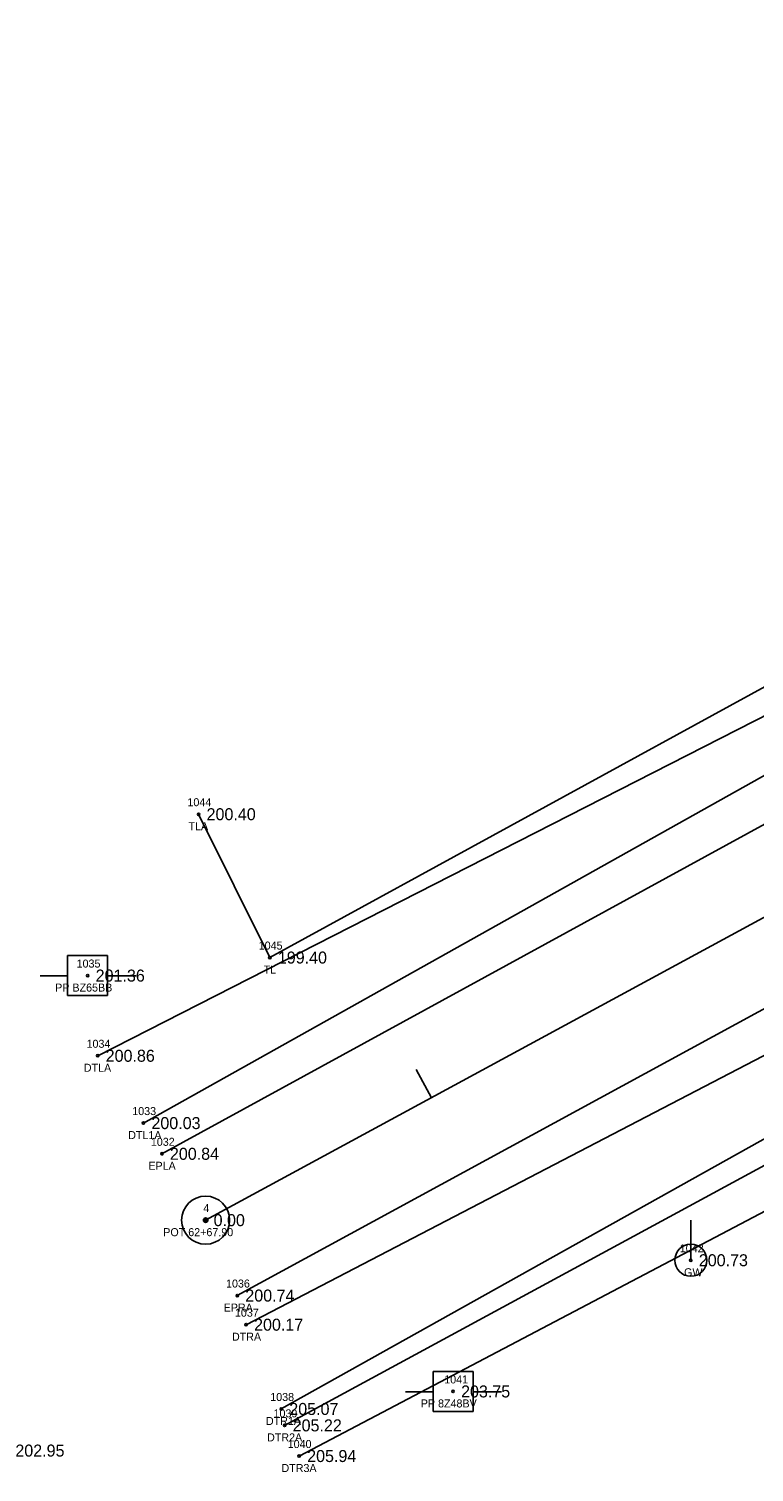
# Model space of a CAD drawing. Extents: x 2279339 to 2281902, y 1061267 to 1062892.
# Drawn here: x 2279537.7 to 2279628.3, y 1061401.7 to 1061582 of the extents above; entities that cross this region are included whole.
import ezdxf

# ---------------------------------------------------------------- set-up
doc = ezdxf.new("R2010")
doc.units = 0
for name, color, linetype in [('RD_EX_H2O', 7, 'Continuous'), ('RD_EX_H2O_txCode', 7, 'Continuous'), ('RD_EX_Road', 7, 'Continuous'), ('RD_EX_Road_txCode', 7, 'Continuous'), ('RD_EX_TX_H2O_ELEV', 7, 'Continuous'), ('RD_EX_TX_Road_ELEV', 7, 'Continuous'), ('RD_EX_TX_UT_ELEV', 7, 'Continuous'), ('RD_EX_TX_VEG_ELEV', 7, 'Continuous'), ('RD_EX_UT', 7, 'Continuous'), ('RD_EX_UT_txCode', 7, 'Continuous'), ('RD_EX_VEG', 7, 'Continuous'), ('RD_EX_VEG_txCode', 7, 'Continuous'), ('RD_HC_Cl', 7, 'Continuous'), ('RD_HC_Data', 7, 'Continuous'), ('RD_HC_Data_Tic', 7, 'Continuous'), ('RD_HC_Survey_ELEV', 7, 'Continuous'), ('RD_HC_txCode', 7, 'Continuous'), ('RD_SMD_Locator', 7, 'Continuous')]:
    doc.layers.add(name, color=color, linetype=linetype)

msp = doc.modelspace()

# ---------------------------------------------------------------- linework, layer by layer
at = {"layer": 'RD_EX_H2O'}
for points in [[(2279546.29, 1061453.71), (2279630.41, 1061496.6), (2279659.08, 1061511.93), (2279655.3, 1061525.45)], [(2279552, 1061445.3), (2279634.13, 1061491.29), (2279668.82, 1061510.33), (2279666.09, 1061516.71), (2279655.3, 1061525.45)], [(2279564.82, 1061420.11), (2279648.07, 1061463.42), (2279697.17, 1061487.92), (2279700.19, 1061484.6), (2279705.74, 1061483.55)], [(2279569.22, 1061409.58), (2279651.68, 1061455.72), (2279697.08, 1061482.41), (2279717.86, 1061447.1)], [(2279569.64, 1061407.53), (2279652.88, 1061452.64), (2279691.84, 1061472.85), (2279696.06, 1061472.47), (2279695.2, 1061463.42)], [(2279571.45, 1061403.7), (2279656.13, 1061448.23), (2279695.2, 1061463.42)]]:
    msp.add_lwpolyline(points, dxfattribs=at)
at = {"layer": 'RD_EX_Road'}
for points in [[(2279554.31, 1061441.46), (2279636.61, 1061486.51), (2279673.46, 1061506.76), (2279683.06, 1061512.21), (2279723.14, 1061533.54), (2279809.28, 1061580.29), (2279896.91, 1061627.91), (2279977.07, 1061671.02), (2280059.64, 1061715.57), (2280142.91, 1061760.72), (2280228.83, 1061807.06), (2280306.04, 1061849.18), (2280392.98, 1061896.71), (2280482.82, 1061945.75), (2280567.83, 1061991.78), (2280649.94, 1062036.55), (2280660.56, 1062042.19), (2280676.12, 1062050.66), (2280737.28, 1062083.64), (2280828.54, 1062132.77), (2280887.86, 1062164.61), (2280934.91, 1062190.9)], [(2279563.73, 1061423.75), (2279645.81, 1061468.43), (2279687.22, 1061491.24), (2279716.07, 1061507.1), (2279732.53, 1061515.67), (2279819.45, 1061563.03), (2279856.79, 1061583.22), (2279872.52, 1061591.57), (2279906, 1061609.76), (2279987.33, 1061653.65)]]:
    msp.add_lwpolyline(points, dxfattribs=at)
at = {"layer": 'RD_EX_UT'}
for p, q in [((2279547.53, 1061466.24), (2279542.53, 1061466.24)), ((2279542.53, 1061466.24), (2279542.53, 1061461.24)), ((2279547.53, 1061461.24), (2279547.53, 1061466.24)), ((2279539.1, 1061463.68), (2279542.57, 1061463.68)), ((2279547.46, 1061463.68), (2279551.1, 1061463.68)), ((2279542.53, 1061461.24), (2279547.53, 1061461.24)), ((2279620.36, 1061428.16), (2279620.36, 1061433.16)), ((2279593.17, 1061414.27), (2279588.17, 1061414.27)), ((2279588.17, 1061414.27), (2279588.17, 1061409.27)), ((2279593.17, 1061409.27), (2279593.17, 1061414.27)), ((2279584.73, 1061411.71), (2279588.2, 1061411.71)), ((2279593.09, 1061411.71), (2279596.73, 1061411.71)), ((2279588.17, 1061409.27), (2279593.17, 1061409.27))]:
    msp.add_line(p, q, dxfattribs=at)
msp.add_circle((2279620.36, 1061428.16), 2, dxfattribs=at)
at = {"layer": 'RD_EX_VEG'}
msp.add_lwpolyline([(2279558.89, 1061483.89), (2279567.79, 1061465.98), (2279895.37, 1061645.37), (2280383.77, 1061911.19), (2280927.05, 1062203.11)], dxfattribs=at)
at = {"layer": 'RD_HC_Cl'}
msp.add_line((2279559.77, 1061433.17), (2280939.55, 1062181.67), dxfattribs=at)
at = {"layer": 'RD_HC_Data'}
for radius in [3, 0.282]:
    msp.add_circle((2279559.77, 1061433.17), radius, dxfattribs=at)
at = {"layer": 'RD_HC_Data_Tic'}
msp.add_line((2279587.98, 1061448.47), (2279586.07, 1061451.99), dxfattribs=at)
at = {"layer": 'RD_SMD_Locator'}
for centre in [(2279558.89, 1061483.89), (2279567.79, 1061465.98), (2279545.04, 1061463.73), (2279546.29, 1061453.71), (2279552, 1061445.3), (2279554.31, 1061441.46), (2279559.77, 1061433.17), (2279620.36, 1061428.16), (2279563.73, 1061423.75), (2279564.82, 1061420.11), (2279590.67, 1061411.77), (2279569.22, 1061409.58), (2279569.64, 1061407.53), (2279571.45, 1061403.7)]:
    msp.add_circle(centre, 0.15, dxfattribs=at)

# ---------------------------------------------------------------- texts
at = {"layer": 'RD_EX_H2O_txCode'}
for s, p in [('1034', (2279544.9, 1061454.71)), ('DTLA', (2279544.56, 1061451.71)), ('1033', (2279550.61, 1061446.3)), ('DTL1A', (2279550.1, 1061443.3)), ('1037', (2279563.43, 1061421.11)), ('DTRA', (2279563.06, 1061418.11)), ('1038', (2279567.84, 1061410.58)), ('DTR1A', (2279567.3, 1061407.58)), ('1039', (2279568.25, 1061408.53)), ('DTR2A', (2279567.44, 1061405.53)), ('1040', (2279570.02, 1061404.7)), ('DTR3A', (2279569.24, 1061401.7))]:
    msp.add_text(s, height=1, dxfattribs=at).set_placement(p)
at = {"layer": 'RD_EX_Road_txCode'}
for s, p in [('1032', (2279552.93, 1061442.46)), ('EPLA', (2279552.62, 1061439.46)), ('1036', (2279562.32, 1061424.75)), ('EPRA', (2279562.02, 1061421.75))]:
    msp.add_text(s, height=1, dxfattribs=at).set_placement(p)
at = {"layer": 'RD_EX_TX_H2O_ELEV'}
for s, p in [('200.86', (2279547.29, 1061452.96)), ('200.03', (2279553, 1061444.55)), ('200.17', (2279565.82, 1061419.36)), ('205.07', (2279570.22, 1061408.83)), ('205.22', (2279570.64, 1061406.78)), ('205.94', (2279572.45, 1061402.95))]:
    msp.add_text(s, height=1.5, dxfattribs=at).set_placement(p)
at = {"layer": 'RD_EX_TX_Road_ELEV'}
for s, p in [('200.84', (2279555.31, 1061440.71)), ('200.74', (2279564.73, 1061423))]:
    msp.add_text(s, height=1.5, dxfattribs=at).set_placement(p)
at = {"layer": 'RD_EX_TX_UT_ELEV'}
msp.add_text('200.73', height=1.5, dxfattribs=at).set_placement((2279621.36, 1061427.41))
at = {"layer": 'RD_EX_TX_VEG_ELEV'}
for s, p in [('200.40', (2279559.89, 1061483.14)), ('199.40', (2279568.79, 1061465.23))]:
    msp.add_text(s, height=1.5, dxfattribs=at).set_placement(p)
at = {"layer": 'RD_EX_UT_txCode'}
for s, p in [('1035', (2279543.66, 1061464.73)), ('PP BZ65BB', (2279540.98, 1061461.73)), ('1042', (2279618.98, 1061429.16)), ('GW', (2279619.52, 1061426.16)), ('1041', (2279589.57, 1061412.77)), ('PP 8Z48BV', (2279586.64, 1061409.77))]:
    msp.add_text(s, height=1, dxfattribs=at).set_placement(p)
at = {"layer": 'RD_EX_VEG_txCode'}
for s, p in [('1044', (2279557.5, 1061484.89)), ('TLA', (2279557.63, 1061481.89)), ('1045', (2279566.4, 1061466.98)), ('TL', (2279567.01, 1061463.98))]:
    msp.add_text(s, height=1, dxfattribs=at).set_placement(p)
at = {"layer": 'RD_HC_Survey_ELEV'}
for s, p in [('201.36', (2279546.04, 1061462.98)), ('0.00', (2279560.77, 1061432.42)), ('203.75', (2279591.67, 1061411.02)), ('202.95', (2279536.01, 1061403.63))]:
    msp.add_text(s, height=1.5, dxfattribs=at).set_placement(p)
at = {"layer": 'RD_HC_txCode'}
for s, p in [('4', (2279559.48, 1061434.17)), ('POT 62+67.90', (2279554.48, 1061431.17))]:
    msp.add_text(s, height=1, dxfattribs=at).set_placement(p)

doc.saveas('drawing.dxf')
